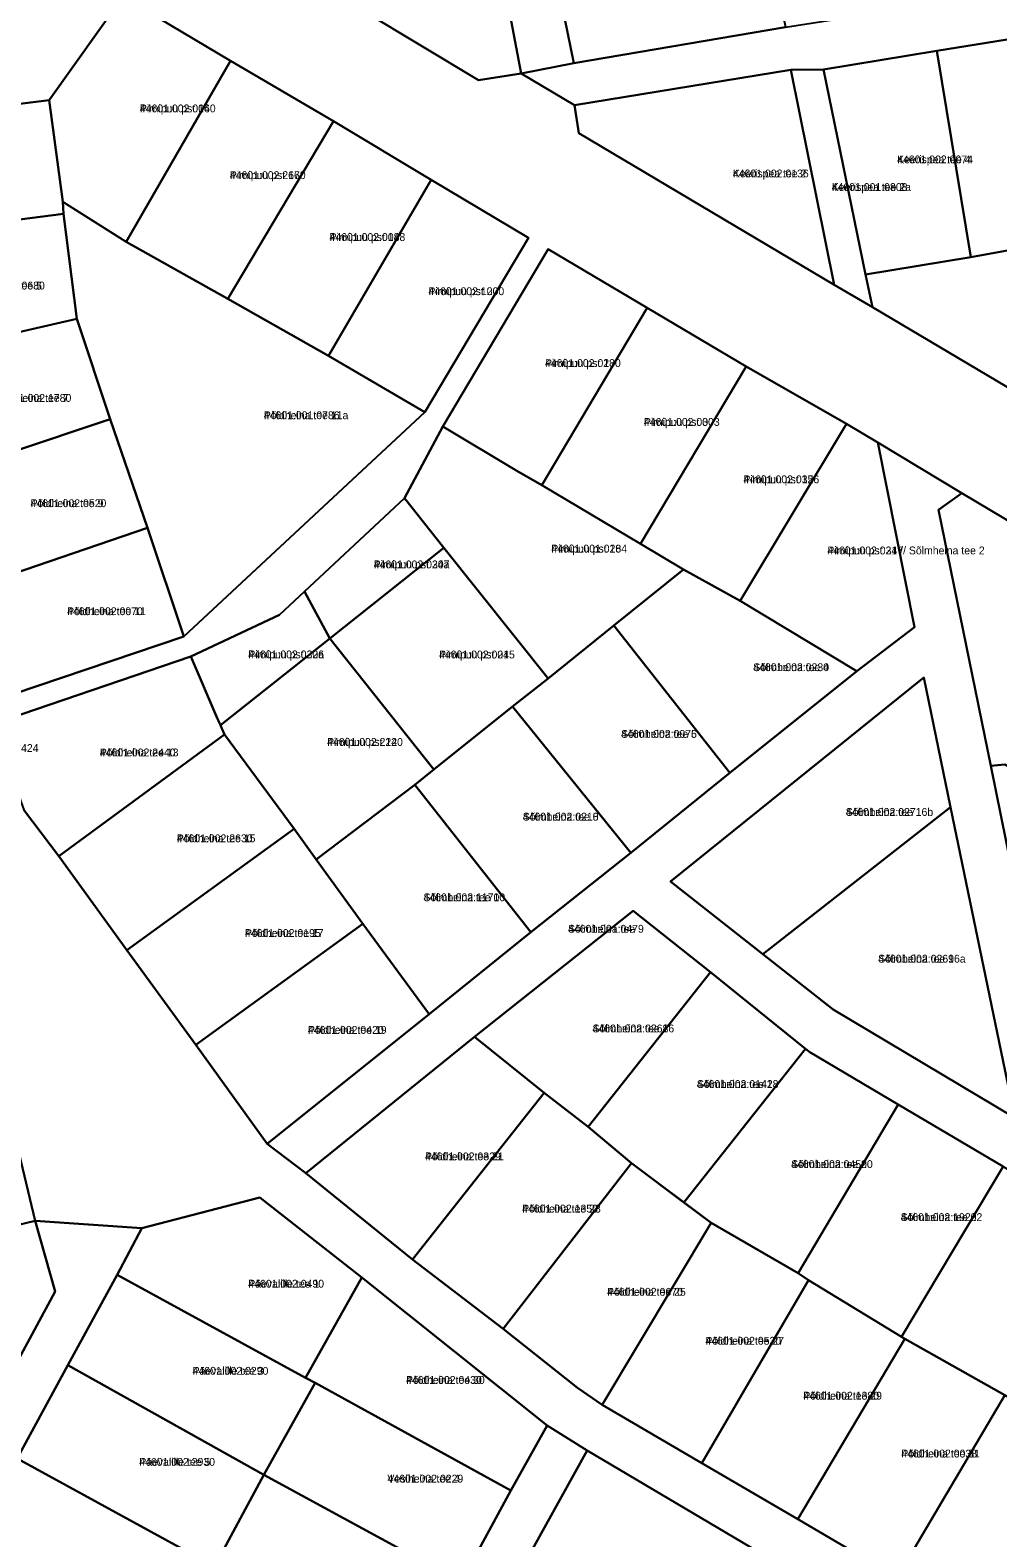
# Model space of a CAD drawing. Extents: x 551843 to 558501, y 6589003 to 6595718.
# Drawn here: x 552659.9 to 552845.1, y 6593483.8 to 6593772.3 of the extents above; entities that cross this region are included whole.
import ezdxf

# ---------------------------------------------------------------- set-up
doc = ezdxf.new("R2010")
doc.units = 0
for name, color, linetype in [('L_AADRESS', 7, 'Continuous'), ('PIIR', 7, 'Continuous'), ('TUNNUS', 7, 'Continuous')]:
    doc.layers.add(name, color=color, linetype=linetype)

msp = doc.modelspace()

# ---------------------------------------------------------------- linework, layer by layer
at = {"layer": 'PIIR'}
for points in [[(552720.71, 6593938.38), (552729.85, 6593938.48), (552738.94, 6593891.69), (552743.13, 6593870.44), (552747.25, 6593849.58), (552751.37, 6593828.72), (552755.61, 6593807.08), (552759.82, 6593786.31), (552763.93, 6593765.95), (552753.85, 6593763.99), (552747.41, 6593797.97), (552743.06, 6593820.95), (552738.78, 6593843.49), (552734.59, 6593865.63), (552733.5, 6593871.8), (552726.2, 6593909.74)], [(552643.8, 6593798.67), (552677.65, 6593778.72), (552663.55, 6593758.85), (552646.76, 6593756.77), (552641.63, 6593796.6)], [(552747.41, 6593797.97), (552753.85, 6593763.99), (552745.71, 6593762.7), (552712.63, 6593782.63), (552711.02, 6593789.86)], [(552763.93, 6593765.95), (552759.82, 6593786.31), (552800.22, 6593794.3), (552803.2, 6593779.07), (552804.44, 6593772.82)], [(552663.55, 6593758.85), (552677.65, 6593778.72), (552698.29, 6593766.39), (552678.31, 6593731.79), (552666.19, 6593739.43)], [(552854.39, 6593771.71), (552861.42, 6593732.71), (552859.5, 6593732.41), (552839.93, 6593728.82), (552833.44, 6593768.29)], [(552678.31, 6593731.79), (552698.29, 6593766.39), (552717.96, 6593754.82), (552697.78, 6593720.83)], [(552833.44, 6593768.29), (552839.93, 6593728.82), (552819.79, 6593725.53), (552811.71, 6593764.74)], [(552805.49, 6593764.65), (552813.78, 6593723.53), (552764.93, 6593752.54), (552764.06, 6593757.91)], [(552819.79, 6593725.53), (552821.1, 6593719.29), (552813.78, 6593723.53), (552805.49, 6593764.65), (552811.71, 6593764.74)], [(552624.25, 6593754.29), (552646.76, 6593756.77), (552663.55, 6593758.85), (552666.19, 6593739.43), (552666.3, 6593737.11), (552627.12, 6593732.09)], [(552717.96, 6593754.82), (552736.64, 6593743.61), (552716.99, 6593709.92), (552697.78, 6593720.83)], [(552716.99, 6593709.92), (552736.64, 6593743.61), (552755.3, 6593732.51), (552735.43, 6593699.15)], [(552627.12, 6593732.09), (552666.3, 6593737.11), (552668.87, 6593717.03), (552630.18, 6593708.17)], [(552735.43, 6593699.15), (552689.32, 6593656.23), (552682.36, 6593677.03), (552675.27, 6593697.83), (552668.87, 6593717.03), (552666.3, 6593737.11), (552666.19, 6593739.43), (552678.31, 6593731.79), (552697.78, 6593720.83), (552716.99, 6593709.92)], [(552821.1, 6593719.29), (552819.79, 6593725.53), (552839.93, 6593728.82), (552859.5, 6593732.41), (552865.76, 6593694.68), (552863.28, 6593694.26)], [(552778, 6593719.11), (552757.81, 6593685.19), (552753.07, 6593687.93), (552738.88, 6593696.43), (552759.05, 6593730.39)], [(552630.18, 6593708.17), (552668.87, 6593717.03), (552675.27, 6593697.83), (552637.59, 6593685.25)], [(552778, 6593719.11), (552796.92, 6593707.88), (552776.71, 6593673.96), (552757.81, 6593685.19)], [(552816.1, 6593696.94), (552795.77, 6593663.07), (552784.94, 6593669.07), (552776.71, 6593673.96), (552796.92, 6593707.88)], [(552644.69, 6593664.18), (552637.59, 6593685.25), (552675.27, 6593697.83), (552682.36, 6593677.03)], [(552731.53, 6593682.69), (552738.88, 6593696.43), (552753.07, 6593687.93), (552755.18, 6593686.71), (552757.81, 6593685.19), (552776.71, 6593673.96), (552784.94, 6593669.07), (552771.61, 6593658.32), (552759.04, 6593648.19), (552739.08, 6593673.2)], [(552816.1, 6593696.94), (552822.11, 6593693.34), (552829.14, 6593658.04), (552818.14, 6593649.64), (552795.77, 6593663.07)], [(552712.42, 6593664.88), (552731.53, 6593682.69), (552739.08, 6593673.2), (552717.3, 6593655.89)], [(552838.18, 6593683.65), (552867, 6593666.54), (552886.26, 6593655.11), (552866.29, 6593620.87), (552846.42, 6593631.76), (552843.75, 6593631.48), (552833.76, 6593680.47)], [(552651.9, 6593643.62), (552644.69, 6593664.18), (552682.36, 6593677.03), (552689.32, 6593656.23)], [(552737.16, 6593630.81), (552717.3, 6593655.89), (552739.08, 6593673.2), (552759.04, 6593648.19), (552752.2, 6593642.85)], [(552795.77, 6593663.07), (552818.14, 6593649.64), (552793.79, 6593630.16), (552771.61, 6593658.32), (552784.94, 6593669.07)], [(552690.68, 6593652.43), (552707.61, 6593660.4), (552712.42, 6593664.88), (552717.3, 6593655.89), (552696.34, 6593639.26), (552695.58, 6593640.93)], [(552696.34, 6593639.26), (552717.3, 6593655.89), (552737.16, 6593630.81), (552733.52, 6593627.84), (552714.65, 6593613.6), (552710.43, 6593619.42), (552697.14, 6593637.51)], [(552793.79, 6593630.16), (552774.86, 6593614.85), (552752.2, 6593642.85), (552759.04, 6593648.19), (552771.61, 6593658.32)], [(552695.58, 6593640.93), (552697.14, 6593637.51), (552665.39, 6593614.19), (552658.86, 6593622.86), (552652.84, 6593639.55), (552690.68, 6593652.43)], [(552782.43, 6593609.37), (552830.93, 6593648.38), (552836.06, 6593623.58), (552800.13, 6593595.47)], [(552830.93, 6593648.38), (552782.43, 6593609.37), (552800.13, 6593595.47), (552813.61, 6593584.89), (552848.37, 6593564.13), (552836.06, 6593623.58)], [(552737.16, 6593630.81), (552752.2, 6593642.85), (552774.86, 6593614.85), (552755.76, 6593599.67), (552733.52, 6593627.84)], [(552665.39, 6593614.19), (552697.14, 6593637.51), (552710.43, 6593619.42), (552678.44, 6593596.25)], [(552846.42, 6593631.76), (552866.29, 6593620.87), (552885.11, 6593609.17), (552904.22, 6593597.92), (552901.22, 6593591.79), (552878.99, 6593598.88), (552851.49, 6593593.45), (552843.75, 6593631.48)], [(552723.6, 6593601.24), (552714.65, 6593613.6), (552733.52, 6593627.84), (552755.76, 6593599.67), (552736.3, 6593583.99)], [(552800.13, 6593595.47), (552836.06, 6593623.58), (552848.37, 6593564.13), (552813.61, 6593584.89)], [(552691.64, 6593578.09), (552678.44, 6593596.25), (552710.43, 6593619.42), (552714.65, 6593613.6), (552723.6, 6593601.24)], [(552723.6, 6593601.24), (552736.3, 6593583.99), (552705.28, 6593559.2), (552691.64, 6593578.09)], [(552744.94, 6593579.63), (552775.3, 6593603.73), (552790.14, 6593591.99), (552766.73, 6593562.41), (552758.27, 6593568.92)], [(552808.27, 6593577.35), (552785.03, 6593547.95), (552775.02, 6593555.46), (552766.73, 6593562.41), (552790.14, 6593591.99)], [(552712.69, 6593553.58), (552744.94, 6593579.63), (552758.27, 6593568.92), (552733.11, 6593537.05)], [(552809.12, 6593576.69), (552826.04, 6593566.7), (552806.89, 6593534.41), (552790.24, 6593544.04), (552785.03, 6593547.95), (552808.27, 6593577.35)], [(552733.11, 6593537.05), (552758.27, 6593568.92), (552766.73, 6593562.41), (552775.02, 6593555.46), (552750.41, 6593523.76)], [(552846.1, 6593554.84), (552826.66, 6593522.26), (552808.87, 6593533.09), (552806.89, 6593534.41), (552826.04, 6593566.7)], [(552656.12, 6593564.46), (552660.92, 6593544.41), (552620.85, 6593534.78), (552616.06, 6593554.82)], [(552764.67, 6593512.47), (552750.41, 6593523.76), (552775.02, 6593555.46), (552790.24, 6593544.04), (552769.4, 6593509.26)], [(552866.16, 6593543), (552847.08, 6593510.72), (552846.41, 6593511.09), (552827.29, 6593521.85), (552826.66, 6593522.26), (552846.1, 6593554.84)], [(552681.3, 6593543.01), (552703.86, 6593548.9), (552723.38, 6593533.61), (552712.59, 6593514.43), (552676.56, 6593534.11)], [(552660.92, 6593544.41), (552681.3, 6593543.01), (552676.56, 6593534.11), (552667.17, 6593516.83), (552657.46, 6593498.94), (552647.84, 6593481.41), (552638.03, 6593464.12), (552628.37, 6593446.6), (552618.71, 6593429.08), (552609.04, 6593411.57), (552599.39, 6593394.06), (552591.99, 6593398.44), (552602.33, 6593417.19), (552612.65, 6593435.92), (552622.77, 6593454.66), (552632.95, 6593473.18), (552643.15, 6593492.04), (552653.7, 6593510.58), (552664.72, 6593530.92)], [(552620.85, 6593534.78), (552660.92, 6593544.41), (552664.72, 6593530.92), (552653.7, 6593510.58), (552618.35, 6593530.28)], [(552788.42, 6593498.05), (552769.4, 6593509.26), (552790.24, 6593544.04), (552806.89, 6593534.41), (552808.87, 6593533.09)], [(552712.59, 6593514.43), (552714.46, 6593513.43), (552704.66, 6593495.87), (552667.17, 6593516.83), (552676.56, 6593534.11)], [(552712.59, 6593514.43), (552723.38, 6593533.61), (552758.88, 6593505.25), (552751.91, 6593492.86), (552714.46, 6593513.43)], [(552826.66, 6593522.26), (552827.29, 6593521.85), (552806.82, 6593487.36), (552788.42, 6593498.05), (552808.87, 6593533.09)], [(552846.41, 6593511.09), (552825.8, 6593476.22), (552806.82, 6593487.36), (552827.29, 6593521.85)], [(552667.17, 6593516.83), (552704.66, 6593495.87), (552695.23, 6593478.3), (552657.46, 6593498.94)], [(552742.42, 6593475.29), (552704.66, 6593495.87), (552714.46, 6593513.43), (552751.91, 6593492.86)], [(552865.01, 6593500.1), (552844.4, 6593465.23), (552825.8, 6593476.22), (552846.41, 6593511.09), (552847.08, 6593510.72)], [(552751.91, 6593492.86), (552758.88, 6593505.25), (552766.49, 6593500.52), (552756.06, 6593481.6), (552745.63, 6593462.31), (552735.44, 6593443.26), (552724.97, 6593424.24), (552714.47, 6593405.23), (552703.99, 6593386.21), (552693.51, 6593367.19), (552683.03, 6593348.18), (552674.95, 6593352.34), (552684.6, 6593369.82), (552693.98, 6593387.52), (552703.66, 6593405.04), (552713.32, 6593422.59), (552723.01, 6593440.07), (552732.91, 6593457.71), (552742.42, 6593475.29)], [(552756.06, 6593481.6), (552766.49, 6593500.52), (552800.91, 6593480.16), (552791.04, 6593462.01)], [(552657.46, 6593498.94), (552695.23, 6593478.3), (552685.33, 6593460.85), (552647.84, 6593481.41)], [(552742.42, 6593475.29), (552732.91, 6593457.71), (552695.23, 6593478.3), (552704.66, 6593495.87)]]:
    msp.add_lwpolyline(points, close=True, dxfattribs=at)
for points in [[(552645.15, 6593824.74), (552679.24, 6593802.97), (552712.63, 6593782.63), (552745.71, 6593762.7), (552753.85, 6593763.99), (552764.06, 6593757.91), (552764.93, 6593752.54), (552813.78, 6593723.53), (552821.1, 6593719.29), (552863.28, 6593694.26)], [(552651.9, 6593643.62), (552689.32, 6593656.23), (552735.43, 6593699.15), (552755.3, 6593732.51), (552736.64, 6593743.61), (552717.96, 6593754.82), (552698.29, 6593766.39), (552677.65, 6593778.72), (552643.8, 6593798.67)], [(552854.39, 6593771.71), (552833.44, 6593768.29), (552811.71, 6593764.74), (552805.49, 6593764.65), (552764.06, 6593757.91), (552753.85, 6593763.99), (552763.93, 6593765.95), (552804.44, 6593772.82), (552842.95, 6593778.87), (552857.84, 6593781.35)], [(552867, 6593666.54), (552838.18, 6593683.65), (552822.11, 6593693.34), (552816.1, 6593696.94), (552796.92, 6593707.88), (552778, 6593719.11), (552759.05, 6593730.39), (552738.88, 6593696.43), (552731.53, 6593682.69), (552712.42, 6593664.88), (552707.61, 6593660.4), (552690.68, 6593652.43), (552652.84, 6593639.55)], [(552846.1, 6593554.84), (552826.04, 6593566.7), (552809.12, 6593576.69), (552808.27, 6593577.35), (552790.14, 6593591.99), (552775.3, 6593603.73), (552744.94, 6593579.63), (552712.69, 6593553.58), (552705.28, 6593559.2), (552736.3, 6593583.99), (552755.76, 6593599.67), (552774.86, 6593614.85), (552793.79, 6593630.16), (552818.14, 6593649.64), (552829.14, 6593658.04), (552822.11, 6593693.34), (552838.18, 6593683.65), (552833.76, 6593680.47), (552843.75, 6593631.48), (552851.49, 6593593.45)], [(552658.86, 6593622.86), (552665.39, 6593614.19), (552678.44, 6593596.25), (552691.64, 6593578.09), (552705.28, 6593559.2), (552712.69, 6593553.58), (552733.11, 6593537.05), (552750.41, 6593523.76), (552764.67, 6593512.47), (552769.4, 6593509.26), (552788.42, 6593498.05), (552806.82, 6593487.36), (552825.8, 6593476.22)], [(552800.91, 6593480.16), (552766.49, 6593500.52), (552758.88, 6593505.25), (552723.38, 6593533.61), (552703.86, 6593548.9), (552681.3, 6593543.01), (552660.92, 6593544.41), (552656.12, 6593564.46)]]:
    msp.add_lwpolyline(points, dxfattribs=at)

# ---------------------------------------------------------------- texts
at = {"layer": 'L_AADRESS'}
for s, p in [('Pirnipuu pst 14', (552680.92, 6593756.54)), ('Keerispea tee 4', (552825.82, 6593746.78)), ('Pirnipuu pst 16', (552698.14, 6593743.77)), ('Keerispea tee 2', (552794.4, 6593744.09)), ('Keerispea tee 2a', (552813.3, 6593741.49)), ('Pirnipuu pst 18', (552717.21, 6593731.93)), ('Põldheina tee 5', (552648.24, 6593722.64)), ('Pirnipuu pst 20', (552736.14, 6593721.56)), ('Pirnipuu pst 28', (552758.44, 6593707.81)), ('Põldheina tee 7', (552653.31, 6593701.14)), ('Põldheina tee 11a', (552704.64, 6593697.83)), ('Pirnipuu pst 30', (552777.37, 6593696.55)), ('Pirnipuu pst 32', (552796.41, 6593685.57)), ('Põldheina tee 9', (552660.01, 6593681)), ('Pirnipuu pst 26', (552759.64, 6593672.31)), ('Pirnipuu pst 34 // Sõlmheina tee 2', (552812.46, 6593671.96)), ('Pirnipuu pst 24a', (552725.66, 6593669.29)), ('Põldheina tee 11', (552667, 6593660.33)), ('Pirnipuu pst 22a', (552701.66, 6593652.07)), ('Pirnipuu pst 24', (552738.17, 6593652.05)), ('Sõlmheina tee 4', (552798.29, 6593649.62)), ('Pirnipuu pst 22', (552716.75, 6593635.32)), ('Sõlmheina tee 6', (552773, 6593636.86)), ('Põldheina tee 13', (552673.26, 6593633.31)), ('Sõlmheina tee 8', (552754.19, 6593621.02)), ('Sõlmheina tee 16b', (552815.99, 6593621.92)), ('Põldheina tee 15', (552687.99, 6593616.88)), ('Sõlmheina tee 10', (552735.2, 6593605.59)), ('Sõlmheina tee', (552762.85, 6593599.57)), ('Põldheina tee 17', (552701.03, 6593598.76)), ('Sõlmheina tee 16a', (552822.2, 6593593.85)), ('Põldheina tee 19', (552713.08, 6593580.22)), ('Sõlmheina tee 16', (552767.54, 6593580.5)), ('Sõlmheina tee 18', (552787.5, 6593569.86)), ('Põldheina tee 21', (552735.48, 6593556.02)), ('Sõlmheina tee 20', (552805.54, 6593554.54)), ('Põldheina tee 23', (552754.07, 6593546.03)), ('Sõlmheina tee 22', (552826.5, 6593544.4)), ('Päevalille tee 1', (552701.66, 6593531.66)), ('Põldheina tee 25', (552770.32, 6593530.11)), ('Põldheina tee 27', (552789.13, 6593520.74)), ('Päevalille tee 3', (552691.01, 6593514.99)), ('Põldheina tee 30', (552731.85, 6593513.24)), ('Põldheina tee 29', (552807.86, 6593510.23)), ('Põldheina tee 31', (552826.61, 6593499.16)), ('Päevalille tee 5', (552680.8, 6593497.57)), ('Vesiheina tee 4', (552728.3, 6593494.36))]:
    msp.add_text(s, height=1.5, dxfattribs=at).set_placement(p)
at = {"layer": 'TUNNUS'}
for s, p in [('44601:002:0060', (552680.92, 6593756.54)), ('44601:002:0074', (552825.82, 6593746.78)), ('44601:002:0136', (552794.4, 6593744.09)), ('44601:002:2670', (552698.14, 6593743.77)), ('44601:001:0808', (552813.3, 6593741.49)), ('44601:002:0048', (552717.21, 6593731.93)), ('44601:002:0680', (552648.24, 6593722.64)), ('44601:002:1000', (552736.14, 6593721.56)), ('44601:002:0130', (552758.44, 6593707.81)), ('44601:002:1780', (552653.31, 6593701.14)), ('44601:001:0786', (552704.64, 6593697.83)), ('44601:002:0003', (552777.37, 6593696.55)), ('44601:002:0156', (552796.41, 6593685.57)), ('44601:002:0520', (552660.01, 6593681)), ('44601:001:0184', (552759.64, 6593672.31)), ('44601:002:0217', (552812.46, 6593671.96)), ('44601:002:0307', (552725.66, 6593669.29)), ('44601:002:0070', (552667, 6593660.33)), ('44601:002:0306', (552701.66, 6593652.07)), ('44601:002:0015', (552738.17, 6593652.05)), ('44601:002:0230', (552798.29, 6593649.62)), ('44601:002:2140', (552716.75, 6593635.32)), ('44601:002:0075', (552773, 6593636.86)), ('44601:001:0424', (552647.03, 6593634.15)), ('44601:002:2440', (552673.26, 6593633.31)), ('44601:002:0210', (552754.19, 6593621.02)), ('44601:002:0271', (552815.99, 6593621.92)), ('44601:002:2630', (552687.99, 6593616.88)), ('44601:002:1170', (552735.2, 6593605.59)), ('44601:001:0479', (552762.85, 6593599.57)), ('44601:002:0195', (552701.03, 6593598.76)), ('44601:002:0269', (552822.2, 6593593.85)), ('44601:002:0420', (552713.08, 6593580.22)), ('44601:002:0268', (552767.54, 6593580.5)), ('44601:002:0142', (552787.5, 6593569.86)), ('44601:002:0329', (552735.48, 6593556.02)), ('44601:002:0450', (552805.54, 6593554.54)), ('44601:002:1350', (552754.07, 6593546.03)), ('44601:002:1920', (552826.5, 6593544.4)), ('44601:002:0490', (552701.66, 6593531.66)), ('44601:002:0670', (552770.32, 6593530.11)), ('44601:002:0530', (552789.13, 6593520.74)), ('44601:002:0290', (552691.01, 6593514.99)), ('44601:002:0430', (552731.85, 6593513.24)), ('44601:002:1380', (552807.86, 6593510.23)), ('44601:002:0038', (552826.61, 6593499.16)), ('44601:002:2930', (552680.8, 6593497.57)), ('44601:002:0229', (552728.3, 6593494.36))]:
    msp.add_text(s, height=1.5, dxfattribs=at).set_placement(p)

doc.saveas('drawing.dxf')
